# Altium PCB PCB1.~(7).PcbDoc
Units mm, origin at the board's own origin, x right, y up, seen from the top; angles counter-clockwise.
Board outline 72.39 x 22.86 mm, 3 copper layers (Top Layer, Internal Plane 1, Bottom Layer); 15 components, 13 nets, 51 pads, 0 vias.
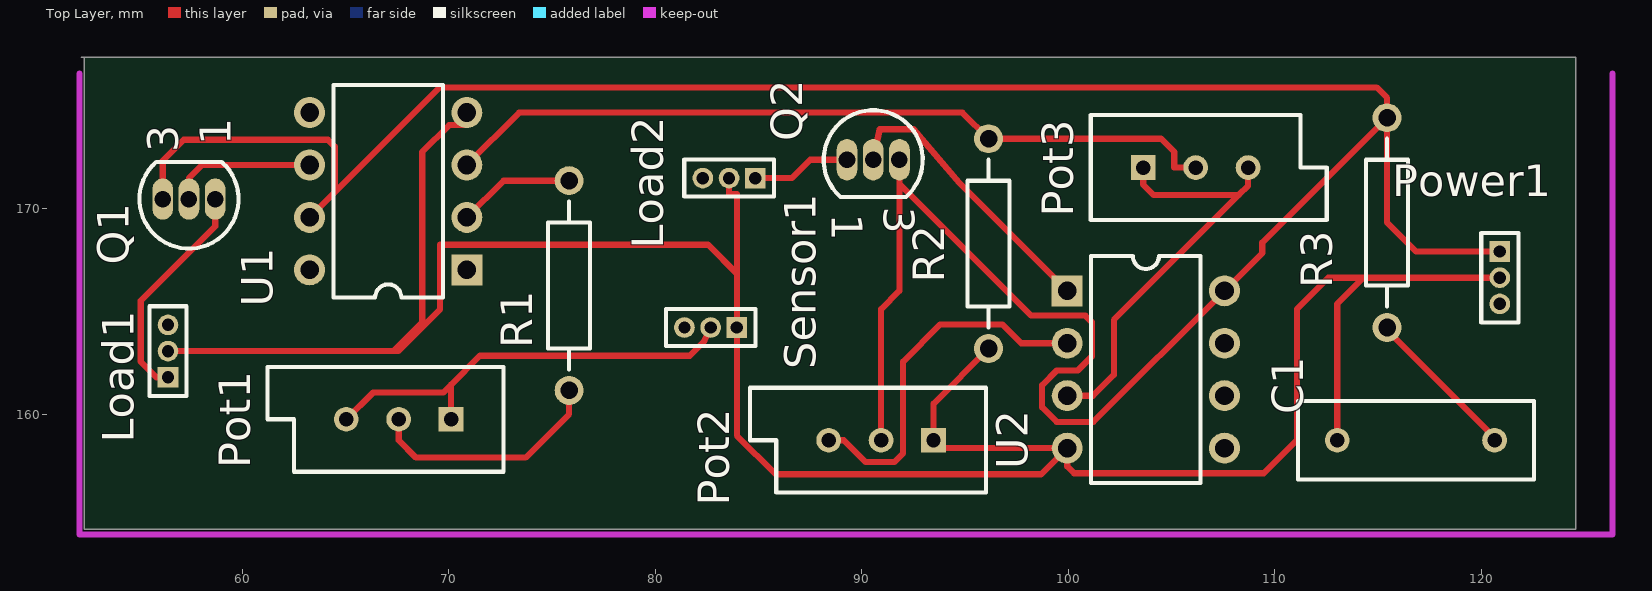
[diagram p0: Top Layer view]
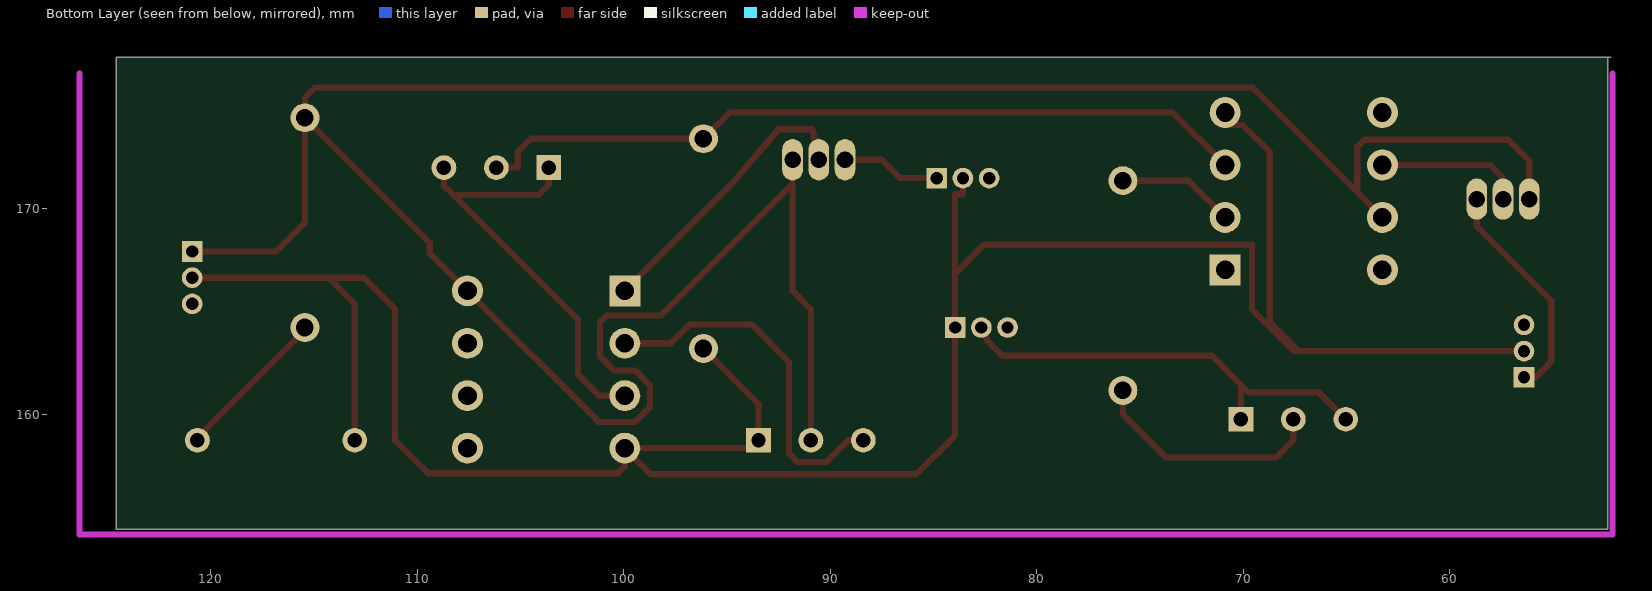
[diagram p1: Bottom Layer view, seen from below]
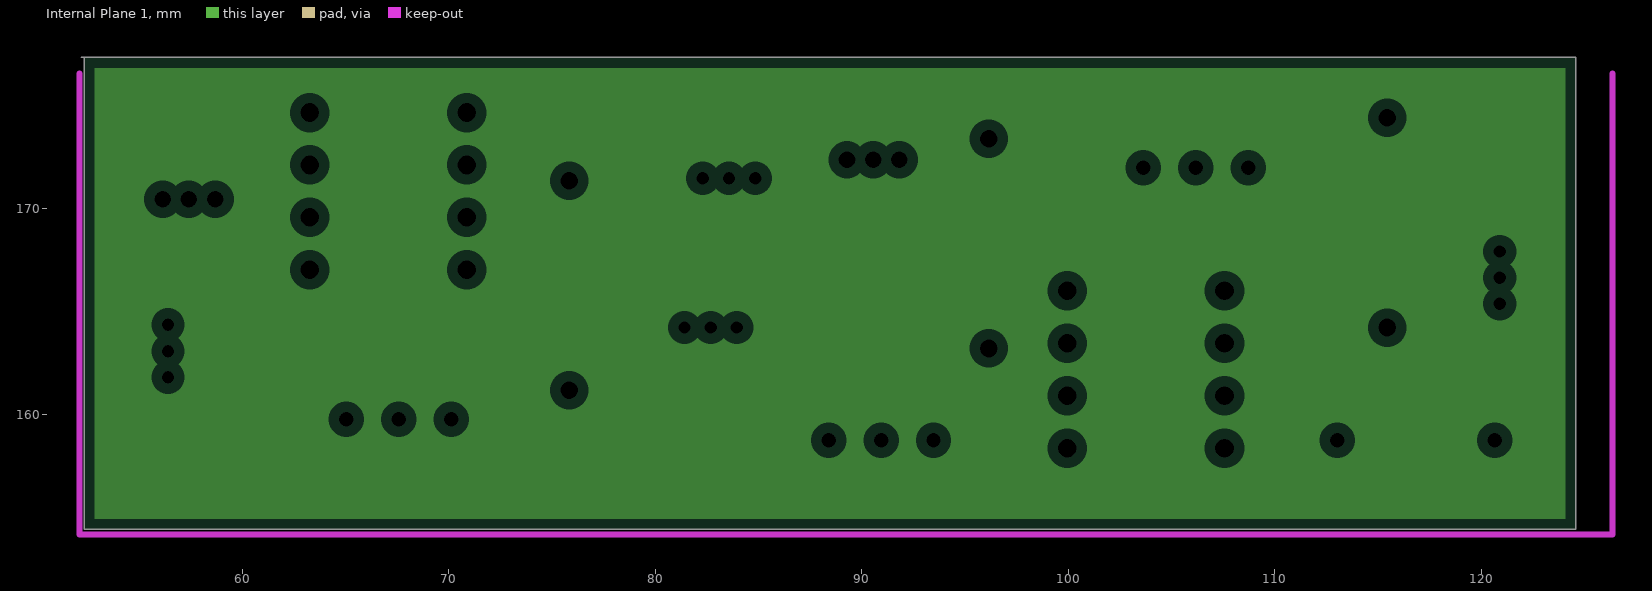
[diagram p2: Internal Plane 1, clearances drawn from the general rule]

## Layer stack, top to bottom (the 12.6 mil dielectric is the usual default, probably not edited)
Top Layer: signal copper 0.0356
Dielectric: dielectric 0.32, FR-4, Dk 4.8
Internal Plane 1: plane copper 0.0356
Dielectric: dielectric 0.32, FR-4, Dk 4.8
Bottom Layer: signal copper 0.0356

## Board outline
52.197,177.292 124.587,177.292 124.587,154.432 52.324,154.432 52.324,177.292

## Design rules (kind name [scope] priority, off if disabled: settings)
Clearance [All] p1: gap=0.3
ComponentClearance [All] p1: gap=0.254 collisioncheckmode=3 verticalgap=0.254
PlaneClearance [All] p1: clearance=0.508
PlaneConnect [All] p1: planeconnectstyle=Relief reliefexpansion=0.508 reliefentries=4 reliefconductorwidth=0.254 reliefairgap=0.254
PolygonConnect [All] p1: connectstyle=Relief reliefconductorwidth=0.254 reliefentries=4 polygonreliefangle="90 Angle"
RoomDefinition Sheet1 [InComponentClass('Sheet1')] p1: confinementstyle=ConfineIn formatcopy=TRUE lockcomponents=FALSE outline 52.324,154.559 124.46,154.559 124.46,177.038 52.324,177.038
RoutingVias [All] p1: holewidth=0.8 width=1.6 viastyle="Through Hole" minholewidth=0.711 minwidth=1.27 maxholewidth=0.711 maxwidth=1.27
SolderMaskExpansion [All] p1: expansion=0.102
TestPointUsage [All] p1: valid=0 allowmultiple=FALSE
Testpoint [All] p1: side=15 testpointundercomponent=TRUE minsize=1.016 maxsize=2.54 preferedsize=1.524 minholesize=0 maxholesize=1.016 preferedholesize=0.813 testpointgrid=0.025 style=1023 order=0-112345678
Width [All] p1: maxlimit=0.3 minlimit=0.3 preferedwidth=0.3
16 further rules are at their usual default settings.

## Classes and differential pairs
component class Sheet1: Q2 R1 R2 R3 Sensor1 U1 U2

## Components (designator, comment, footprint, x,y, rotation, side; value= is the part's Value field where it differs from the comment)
C1 "Cap" RAD-0.3 116.84,158.75 r0 top
Load1 "MHDR1X3" MHDR1X3 56.388,161.798 r90 top
Load2 "MHDR1X3" MHDR1X3 84.836,171.45 r180 top
Pot1 "RPot" VR5 67.564,159.766 r180 top
Pot2 "RPot" VR5 90.932,158.75 r180 top (schematic designator Pot3)
Pot3 "RPot" VR5 106.172,171.958 r0 top (schematic designator Pot2)
Power1 "MHDR1X3" MHDR1X3 120.904,167.894 r270 top (schematic designator Power)
Q1 "BC547A" SOT54 57.404,170.434 r90 top
Q2 "BC547A" SOT54 90.551,172.339 r270 top
R1 "Res2" AXIAL-0.4 75.819,166.243 r90 top
R2 "Res2" AXIAL-0.4 96.139,168.275 r90 top
R3 "Res2" AXIAL-0.4 115.443,169.291 r90 top
Sensor1 "MHDR1X3" MHDR1X3 83.947,164.211 r180 top (schematic designator Sensor)
U1 "LM741J/883" N08E 67.056,170.815 r90 top
U2 "LM393P" P008 103.759,162.179 r270 top

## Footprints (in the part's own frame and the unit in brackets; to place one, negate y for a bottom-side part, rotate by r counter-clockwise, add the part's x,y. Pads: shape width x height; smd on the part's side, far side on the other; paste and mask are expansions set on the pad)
AXIAL-0.4 [mm] "Resistor; 2 Leads"
  round 1.4 hole 0.85: 1(-5.08,0) 2(5.08,0)
  silkscreen extent -4.06,-1.02 4.06,1.02
MHDR1X3 [mm] "Connector; Header; 3 Position"
  rect 1x1 hole 0.6: 1(0,0)
  round 1 hole 0.6: 2(1.27,0) 3(2.54,0)
  silkscreen extent -0.9,-0.9 3.44,0.9
N08E [mm] "DIP; 8 Leads; Row Spacing 7.62 mm; Pitch 2.54 mm"
  rect 1.5x1.5 hole 0.9: 1(-3.81,-3.81)
  round 1.5 hole 0.9: 2(-1.27,-3.81) 3(1.27,-3.81) 4(3.81,-3.81) 5(3.81,3.81) 6(1.27,3.81) 7(-1.27,3.81) 8(-3.81,3.81)
  silkscreen extent -5.15,-2.65 5.15,2.65
P008 [mm] "DIP; 8 Leads; Row Spacing 7.62 mm; Pitch 2.54 mm"
  rect 1.5x1.5 hole 0.9: 1(-3.81,-3.81)
  round 1.5 hole 0.9: 2(-1.27,-3.81) 3(1.27,-3.81) 4(3.81,-3.81) 5(3.81,3.81) 6(1.27,3.81) 7(-1.27,3.81) 8(-3.81,3.81)
  silkscreen extent -5.5,-2.65 5.5,2.65
RAD-0.3 [mm] "Capacitor; 2 Leads"
  round 1.2 hole 0.7: 1(-3.81,0) 2(3.81,0)
  silkscreen extent -5.71,-1.91 5.71,1.91
SOT54 [mm] "TO, Flat Index; 3 In-Line, Axial Leads; Body Dia. 4.6mm; Leads 0.48 x 0.45 mm (max)"
  oval 2x1 hole 0.8: 1(0,-1.27) 2(0,0) 3(0,1.27)
  silkscreen extent -2.4,-2.4 1.8,2.4
VR5 [mm] "Potentiometer; 3 Leads"
  rect 1.2x1.2 hole 0.7: 1(-2.54,0)
  round 1.2 hole 0.7: 2(0,0) 3(2.54,0)
  silkscreen extent -5.08,-2.54 6.35,2.54

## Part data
C1: "Capacitor"
Load1 Load2 Power1 Sensor1: "Header, 3-Pin"
Pot1 Pot2 Pot3: "Potentiometer"
Q1 Q2: "NPN General-purpose Transistor"
R1 R2 R3: "Resistor"
U1: "Operational Amplifier"
U2: "Dual Differential Comparator"

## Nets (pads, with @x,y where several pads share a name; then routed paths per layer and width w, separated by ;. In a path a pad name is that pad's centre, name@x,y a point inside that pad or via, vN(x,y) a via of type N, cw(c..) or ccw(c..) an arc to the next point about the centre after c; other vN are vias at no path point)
GND: C1.1 Load1.2 Load2.2 Pot2.1 Power1.2 R2.1 Sensor1.1 U1.4 U2.4 | length 128.6
  Top Layer w0.3: Load1.2 67.31,163.068 ; U1.4 70.866,174.015 70.002,174.015 68.707,172.72 68.707,164.465 67.31,163.068 ; Load2.2 83.566,170.663 83.947,170.663 Sensor1.1 ; R2.1 93.472,160.528 Pot2.1 93.853,158.369 U2.4 ; C1.1 113.03,165.354 114.3,166.624 ; Power1.2 114.3,166.624 ; 67.31,163.068 67.539,163.068 69.571,165.1 69.571,168.224 82.55,168.224 83.947,166.827 Sensor1.1 ; Sensor1.1 83.947,158.979 85.826,157.1 98.68,157.1 U2.4 ; U2.4 99.949,157.48 100.279,157.15 109.474,157.15 111.074,158.75 111.074,165.1 112.598,166.624 114.3,166.624
NetC1_2: C1.2 R3.1 | length 7.6
  Top Layer w0.3: R3.1 115.443,164.084 120.65,158.877 C1.2
NetLoad1_1: Load1.1 Q1.1 | length 11
  Top Layer w0.3: Load1.1 55.829,161.798 55.067,162.56 55.067,165.506 58.674,169.113 Q1.1
NetLoad2_1: Load2.1 Q2.1 | length 4.8
  Top Layer w0.3: Load2.1 86.614,171.45 87.503,172.339 Q2.1
NetPot1_1: Pot1.1 Pot1.3 Sensor1.2 | length 21.3
  Top Layer w0.3: Pot1.3 66.319,161.061 69.723,161.061 70.104,161.442 ; Pot1.1 70.104,161.442 ; Sensor1.2 82.372,163.551 81.661,162.839 71.501,162.839 70.104,161.442
NetPot1_2: Pot1.2 R1.1 | length 11.6
  Top Layer w0.3: Pot1.2 67.564,158.75 68.402,157.912 73.711,157.912 75.819,160.02 R1.1
NetPot2_1: Pot3.1 Pot3.3 U2.3 | length 21.1
  Top Layer w0.3: U2.3 101.194,160.909 102.21,161.925 102.21,164.579 108.267,170.637 ; Pot3.1 103.632,171.132 104.127,170.637 108.267,170.637 ; Pot3.3 108.712,171.082 108.267,170.637
NetPot2_2: Pot3.2 R2.2 U1.3 | length 37.9
  Top Layer w0.3: U1.3 73.406,174.625 94.869,174.625 R2.2 104.496,173.355 105.131,172.72 105.131,171.958 Pot3.2
NetPot3_3: Pot2.3 U2.2 | length 17.7
  Top Layer w0.3: Pot2.3 89.12,158.75 90.17,157.7 91.584,157.7 91.999,158.115 91.999,162.56 93.802,164.363 96.812,164.363 97.727,163.449 U2.2
NetQ1_2: Q1.2 U1.6 | length 7.1
  Top Layer w0.3: Q1.2 57.404,171.45 58.039,172.085 U1.6
NetQ2_2: Q2.2 U2.1 | length 14
  Top Layer w0.3: Q2.2 90.868,173.812 92.507,173.812 94.718,171.22 U2.1
NetR1_2: R1.2 U1.2 | length 5.7
  Top Layer w0.3: U1.2 72.644,171.323 R1.2
VCC: Pot2.2 Power1.1 Q1.3 Q2.3 R3.2 U1.7 U2.8 | length 135.2
  Top Layer w0.3: Q1.3 56.134,172.288 57.15,173.304 64.135,173.304 64.465,172.974 64.465,170.764 ; U1.7 64.465,170.764 ; Pot2.2 90.932,165.1 91.821,165.989 91.821,171.171 ; Q2.3 91.821,171.171 ; Power1.1 116.84,167.894 115.443,169.291 R3.2 ; 64.465,170.764 69.545,175.844 114.935,175.844 115.443,175.336 R3.2 ; 91.821,171.171 98.203,164.789 100.825,164.789 101.149,164.465 101.149,162.82 100.457,162.128 99.441,162.128 98.73,161.417 98.73,160.35 99.441,159.639 101.219,159.639 U2.8 109.398,167.818 109.398,168.326 R3.2
pads on no net: Load1.3 Load2.3 Power1.3 Sensor1.3 U1.1 U1.5 U1.8 U2.5 U2.6 U2.7

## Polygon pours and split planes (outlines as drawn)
no net on Internal Plane 1 (split plane): 124.069,154.95 52.842,154.95 52.842,176.774 124.069,176.774

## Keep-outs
Keep-Out Layer:
  lines w0.3: 52.1,176.5 52.1,154.178 126.365,154.178 126.365,176.5

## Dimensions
52.1,154.178 to 126.365,154.178 on Mechanical 1
52.1,154.178 to 52.1,176.5 on Mechanical 1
